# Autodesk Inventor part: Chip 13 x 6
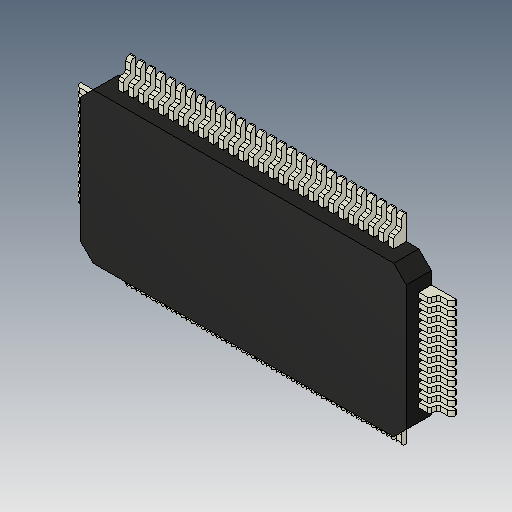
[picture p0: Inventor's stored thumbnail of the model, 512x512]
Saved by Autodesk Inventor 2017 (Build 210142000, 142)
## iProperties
Created: 2005-12
Part Number: Chip 13 x 6
Material: Generic
Document SubType Name: Modeling
Designer: DanielSeverino
Density: 1 g/cm^3
Appearance: Default
Author: DanielSeverino
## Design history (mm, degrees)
feature "Solid1"
body "Solid2"
